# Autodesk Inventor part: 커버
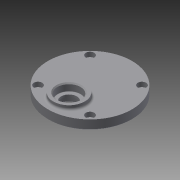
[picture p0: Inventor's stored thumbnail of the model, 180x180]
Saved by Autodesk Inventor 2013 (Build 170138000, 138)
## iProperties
Created: 2015-07
Part Number: 커버
Material: 일반
Document SubType Name: Modeling
Designer: user
Density: 1 g/cm^3
Author: user
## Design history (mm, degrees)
sketch "스케치1"
  geometry: 1 further point
sketch "스케치2"
  geometry: C1 r 40 at (0, 0); 1 further point
  constraints: 1 centre point, 1 coincident
  dimensions: "d0" = 80 diameter of C1
extrude "돌출1" new body sketch "스케치2" stored distance "d1" = 9; taper "d2" = 0 deg
sketch "스케치3"
  geometry: L1 (0, 0)-(0, -20); C1 r 40 at (0, 0) reference; C2 r 15 at (0, -20)
  constraints: 2 end point, 1 centre point, 1 coincident, 1 vertical
  dimensions: "d3" = 20 distance of L1.start L1.end; "d4" = 30 diameter of C2
extrude "돌출2" join sketch "스케치3" distance "d5" = 4; taper "d6" = 0 deg
sketch "스케치4"
  geometry: L1 (0, 0)-(0, -20); C1 r 40 at (0, 0) reference; C2 r 14 at (0, -20)
  constraints: 2 end point, 1 centre point, 1 coincident, 1 vertical
  dimensions: "d7" = 20 distance of L1.start L1.end; "d8" = 28 diameter of C2
extrude "돌출3" join sketch "스케치4" distance "d9" = 3; taper "d10" = 0 deg
sketch "스케치5"
  geometry: L1 (0, 0)-(0, 11); C1 r 40 at (0, 0) reference; C2 r 14 at (0, 11)
  constraints: 2 coincident, 2 end point, 1 centre point, 1 vertical
  dimensions: "d11" = 11 distance of L1.start L1.end; "d12" = 28 diameter of C2
extrude "돌출4" join sketch "스케치5" distance "d13" = 3; taper "d14" = 0 deg
sketch "스케치6"
  geometry: L1 (0, 0)-(0, 35); L2 (0, 0)-(24.749, 24.749); L3 (0, 0)-(35, 0); C1 r 40 at (0, 0) reference; 1 further point
  constraints: 6 end point, 1 coincident, 1 equal length, 1 horizontal, 1 vertical
  dimensions: "d15" = 35 distance of L1.start L1.end; "d16" = 35 distance of L1.start L2.end; "d17" = 45 deg angle of L3 L2
hole "구멍1" sketch "스케치6" at (24.749, 24.749) diameter "d18" = 4.5; stored, may be unused: countersink angle "d22" = 90 deg, drill point angle "d24" = 118 deg; dims "d19" = 6, "d20" = 8, "d21" = 4.4, "d23" = 20
fillet "모깎기1" dims "d28" = 2
sketch "스케치7"
  geometry: C1 r 15 at (0, 0) reference; 1 further point
hole "구멍2" sketch "스케치7" at (0, 0) diameter "d29" = 15; stored, may be unused: countersink angle "d33" = 90 deg, drill point angle "d35" = 118 deg; dims "d30" = 6, "d31" = 22, "d32" = 7, "d34" = 8
sketch "스케치8"
  geometry: C1 r 14 at (0, 0) reference; 1 further point
hole "구멍3" sketch "스케치8" at (0, 0) diameter "d36" = 15; stored, may be unused: countersink angle "d40" = 90 deg, drill point angle "d42" = 118 deg; dims "d37" = 6, "d38" = 22, "d39" = 7, "d41" = 8
sketch "스케치9"
  geometry: C1 r 14 at (0, 0) reference; 1 further point
hole "구멍4" sketch "스케치9" at (0, 0) diameter "d43" = 18; stored, may be unused: countersink angle "d47" = 90 deg, drill point angle "d49" = 0 deg; dims "d44" = 6, "d45" = 22, "d46" = 7, "d48" = 8
fillet "모깎기2" dims "d50" = 2
fillet "모깎기3" dims "d51" = 0.3
chamfer "모따기1" distance "d52" = 1; stored, may be unused: second distance "d53" = 2, angle "d54" = 45 deg
chamfer "모따기2" distance "d55" = 1; stored, may be unused: second distance "d56" = 2, angle "d57" = 45 deg
node "솔리드1"
pattern_circular "원형 패턴1" dims angle "d26" = 360 deg
